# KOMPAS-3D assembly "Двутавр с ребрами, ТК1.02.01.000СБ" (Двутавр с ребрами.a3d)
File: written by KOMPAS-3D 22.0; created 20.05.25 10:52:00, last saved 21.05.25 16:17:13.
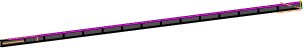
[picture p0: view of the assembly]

Document properties: Автор: TC; Полное имя файла: ТК1.02.01.000 СБ - Двутавр с ребрами Сборочный чертеж.cdw

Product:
- Component [standard]: Двутавр $d 16 ГОСТ 8239-89 ; Ст3сп ГОСТ 535-2005$  | qty 1  | pos. 2  | Масса: 0.943226; Раздел спецификации: Материалы; Рассекать на разрезах: no; additional columns: 16; VIEWPOINT:4c07c083-d9fb-fddf-3729-5b8bea8ed7b8
- Component [detail]: Ребро жесткости  | designation ТК1.02.01.001  | qty 16  | pos. 1  | Материал: Сталь 09Г2С ГОСТ 19281-2014 (density 7850 kg/m3); Масса: 0.212581; Форматы листов документа: A4; source file: Ребро жесткости.cdw, Ребро жесткости.m3d, ТК1.02.01.001 - Ребро жесткости.cdw
- Part/product: Двутавр с ребрами  | designation ТК1.02.01.000СБ
    Масса: 149.81249
    Форматы листов документа: A4@4~3
    source file: ТК1.02.01.000 - Двутавр с ребрами.spw

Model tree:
1. Линейный размер:1  (with: Операция выдавливания:1)
     Значение = 81
2. Линейный размер:2  (with: Операция выдавливания:1)
     Значение = 160
3. Эскиз:1  (with: Операция выдавливания:1, Элемент выдавливания:2, Элемент выдавливания:3)  (labels: Рельс направляющий TBR-C25)
4. Массив по сетке:1  (2 pattern instances)
     Шаг 1 = 717.5; Угол раствора = 90
5. Эскиз:2  (with: Операция выдавливания:1, Элемент выдавливания:1)
6. Массив по сетке:2  (14 pattern instances)
     Шаг 1 = 600; Угол раствора = 90
7. Линейный размер:3  (with: Операция выдавливания:1, Элемент выдавливания:1)
     Значение = 717.5
8. Линейный размер:4  (with: Операция выдавливания:1, Элемент выдавливания:1)
     Значение = 717.5

Referenced files in D:\Рабочая папка\АРХИВ\612\05\Задание №6 - Тележка для крыши\3Д\Рама направляющих\: Ребро жесткости.m3d, Ребро жесткости.cdw, ТК1.02.01.001 - Ребро жесткости.cdw
Referenced files in C:\Program Files\ASCON\KOMPAS-3D v22\Libs\PolynomLib\DATA\vault\Methods\Kompas\3D\: PLib_IBeams_GOST_8239_1501.m3d
Referenced files in D:\Рабочая папка\АРХИВ\612\05\Задание №6 - Тележка для крыши\3Д\: Тележка на рельсах.a3d
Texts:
  Ст3сп
  BOSimple***PART:d1e4b814-fa26-d110-823d-d70c895bd231***SHORTLOC:B94B_A66A3A23F44E414C[16]
  VIEWPOINT:4c07c083-d9fb-fddf-3729-5b8bea8ed7b8
  ТК1.02.01.001
  BOSimple***Material:4ccf0190-16b6-4223-9222-aa108d28a442
  ТК1.02.01.000
  ТК1.02.01.000 СБ
  Двутавр  16 ГОСТ 8239-89 / Ст3сп ГОСТ 535-2005
  ТК1.02.01.001 Ребро жесткости (1)
  ТК1.02.01.001 Ребро жесткости (2)
  ТК1.02.01.001 Ребро жесткости (3)
  ТК1.02.01.001 Ребро жесткости (4)
  ТК1.02.01.001 Ребро жесткости (5)
  ТК1.02.01.001 Ребро жесткости (6)
  ТК1.02.01.001 Ребро жесткости (7)
  ТК1.02.01.001 Ребро жесткости (8)
  ТК1.02.01.001 Ребро жесткости (9)
  ТК1.02.01.001 Ребро жесткости (10)
  ТК1.02.01.001 Ребро жесткости (11)
  ТК1.02.01.001 Ребро жесткости (12)
  ТК1.02.01.001 Ребро жесткости (13)
  ТК1.02.01.001 Ребро жесткости (14)
  ТК1.02.01.001 Ребро жесткости (15)
  ТК1.02.01.001 Ребро жесткости (16)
